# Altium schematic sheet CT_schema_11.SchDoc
size 278 x 170 mm
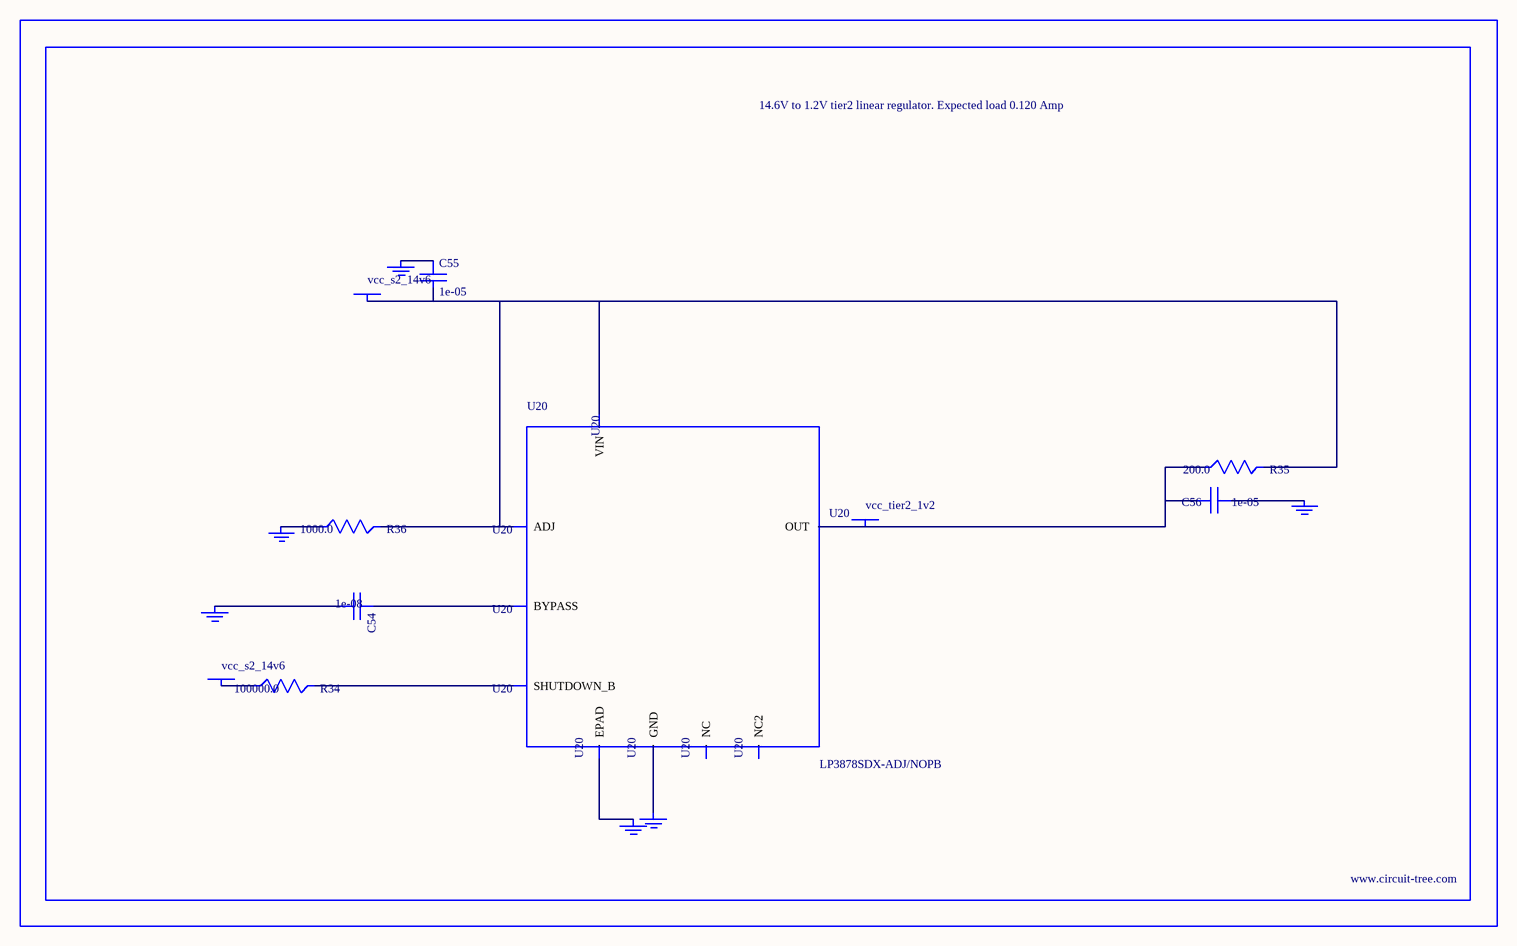
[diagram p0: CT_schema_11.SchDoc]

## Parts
BORDER10  (no value)
C54  1e-08  [C0402]
C55  1e-05  [C1210]
C56  1e-05  [C0805]
GND_INSTANCE_10_0  (no value)
GND_INSTANCE_10_1  (no value)
GND_INSTANCE_10_2  (no value)
GND_INSTANCE_10_3  (no value)
GND_INSTANCE_10_4  (no value)
GND_INSTANCE_10_5  (no value)
POWER_INSTANCE_10_0  vcc_s2_14v6
POWER_INSTANCE_10_1  vcc_s2_14v6
POWER_INSTANCE_10_2  vcc_tier2_1v2
R34  100000.0  [R0603]
R35  200.0  [R0603]
R36  1000.0  [R0603]
U20  LP3878SDX-ADJ/NOPB  [WSON-8]

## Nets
NetC54_1: C54.1 U20.1(BYPASS)
NetC54_2: C54.2 GND_INSTANCE_10_0.0(GND)
NetC55_1: C55.1 GND_INSTANCE_10_1.0(GND)
NetC55_2: C55.2 POWER_INSTANCE_10_0.0(PWR) R35.2 R36.2 U20.4(VIN) U20.6(ADJ)
NetC56_1: C56.1 GND_INSTANCE_10_2.0(GND)
NetC56_2: C56.2 POWER_INSTANCE_10_2.0(PWR) R35.1 U20.5(OUT)
NetGND_INSTANCE_10_3_0: GND_INSTANCE_10_3.0(GND) R36.1
NetGND_INSTANCE_10_4_0: GND_INSTANCE_10_4.0(GND) U20.PAD(EPAD)
NetGND_INSTANCE_10_5_0: GND_INSTANCE_10_5.0(GND) U20.3(GND)
NetPOWER_INSTANCE_10_1_0: POWER_INSTANCE_10_1.0(PWR) R34.1
NetR34_2: R34.2 U20.8(SHUTDOWN_B)

Not connected (* = marked no-connect by the designer): U20 2(NC) 7(NC2)

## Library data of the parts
BORDER10 = BORDER_PAGE10
C54 = C0402C103K3RAC
C55 = C1210C106K5PACTU
C56 = GRM219R60J106ME19D
GND_INSTANCE_10_0-GND_INSTANCE_10_5 = GND
POWER_INSTANCE_10_0-POWER_INSTANCE_10_2 = PWR
R34 = RC0603JR-07100KL
R35 = RC0603JR-07200RL
R36 = RC0603JR-071KL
